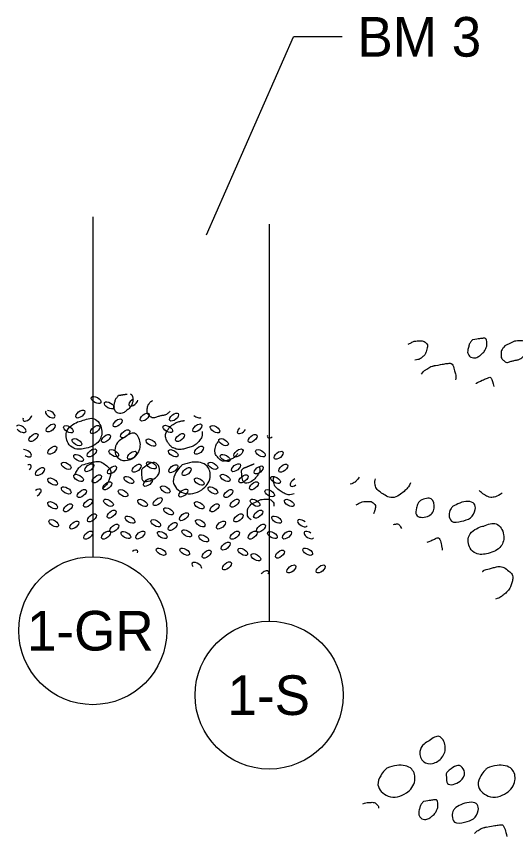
# Model space of a CAD drawing. Extents: x 1785 to 2465, y -264 to 295.
# Drawn here: x 2155.1 to 2190.3, y -12 to 45.9 of the extents above; entities that cross this region are included whole.
import ezdxf

# ---------------------------------------------------------------- set-up
doc = ezdxf.new("R2010")
doc.units = 0
for name, color, linetype in [('DR_P_Culvert', 7, 'Continuous'), ('DR_X_Erosion_Control', 7, 'Continuous'), ('PV_P_Shoulder', 7, 'Continuous'), ('TX_P_1', 7, 'Continuous'), ('TX_P_10', 7, 'Continuous')]:
    doc.layers.add(name, color=color, linetype=linetype)

msp = doc.modelspace()

# ---------------------------------------------------------------- linework, layer by layer
at = {"layer": 'DR_P_Culvert'}
for p, q in [((2160.483, 31.763), (2160.483, 7.757)), ((2172.931, 31.247), (2172.931, 3.206))]:
    msp.add_line(p, q, dxfattribs=at)
at = {"layer": 'DR_X_Erosion_Control'}
for centre, major_axis in [((2160.722, 18.823), (0.33, -0.195)), ((2161.645, 18.444), (0.33, -0.195)), ((2159.602, 17.833), (0.296, 0.243)), ((2162.234, 17.203), (0.296, 0.243)), ((2164.154, 17.618), (0.296, 0.243)), ((2166.226, 17.618), (0.296, 0.243)), ((2157.519, 16.85), (0.296, 0.243)), ((2158.76, 16.761), (0.33, -0.195)), ((2160.654, 16.735), (0.296, 0.243)), ((2165.78, 16.78), (0.33, -0.195)), ((2167.869, 16.85), (0.296, 0.243)), ((2169.11, 16.761), (0.33, -0.195)), ((2156.298, 16.172), (0.296, 0.243)), ((2161.413, 16.104), (0.296, 0.243)), ((2162.771, 16.433), (0.296, 0.243)), ((2166.647, 16.172), (0.296, 0.243)), ((2171.763, 16.104), (0.296, 0.243)), ((2159.365, 15.844), (0.33, -0.195)), ((2164.588, 15.816), (0.33, -0.195)), ((2169.715, 15.844), (0.33, -0.195)), ((2157.628, 15.276), (0.296, 0.243)), ((2160.419, 15.085), (0.296, 0.243)), ((2161.965, 15.066), (0.33, -0.195)), ((2163.252, 14.921), (0.296, 0.243)), ((2166.16, 15.064), (0.33, -0.195)), ((2167.978, 15.276), (0.296, 0.243)), ((2170.768, 15.085), (0.296, 0.243)), ((2172.315, 15.066), (0.33, -0.195)), ((2173.601, 14.921), (0.296, 0.243)), ((2159.479, 14.73), (0.33, -0.195)), ((2164.621, 14.21), (0.33, -0.195)), ((2169.828, 14.73), (0.33, -0.195)), ((2156.76, 13.771), (0.296, 0.243)), ((2158.612, 14.176), (0.33, -0.195)), ((2160.242, 14.044), (0.296, 0.243)), ((2161.846, 13.883), (0.296, 0.243)), ((2163.581, 14.005), (0.296, 0.243)), ((2166.167, 13.974), (0.296, 0.243)), ((2167.11, 13.771), (0.296, 0.243)), ((2168.961, 14.176), (0.33, -0.195)), ((2170.592, 14.044), (0.296, 0.243)), ((2172.196, 13.883), (0.296, 0.243)), ((2173.93, 14.005), (0.296, 0.243)), ((2157.646, 13.063), (0.33, -0.195)), ((2159.479, 13.322), (0.33, -0.195)), ((2160.772, 13.259), (0.296, 0.243)), ((2163.033, 13.178), (0.33, -0.195)), ((2164.378, 13.007), (0.296, 0.243)), ((2167.996, 13.063), (0.33, -0.195)), ((2169.828, 13.322), (0.33, -0.195)), ((2171.122, 13.259), (0.296, 0.243)), ((2173.383, 13.178), (0.33, -0.195)), ((2161.508, 12.767), (0.296, 0.243)), ((2165.604, 12.506), (0.33, -0.195)), ((2171.858, 12.767), (0.296, 0.243)), ((2158.612, 12.441), (0.33, -0.195)), ((2159.712, 12.223), (0.296, 0.243)), ((2162.622, 12.244), (0.33, -0.195)), ((2166.877, 12.256), (0.296, 0.243)), ((2168.961, 12.441), (0.33, -0.195)), ((2170.061, 12.223), (0.296, 0.243)), ((2172.971, 12.244), (0.33, -0.195)), ((2157.646, 11.392), (0.33, -0.195)), ((2160.152, 11.541), (0.296, 0.243)), ((2161.593, 11.568), (0.33, -0.195)), ((2163.998, 11.556), (0.33, -0.195)), ((2165.073, 11.649), (0.296, 0.243)), ((2167.996, 11.392), (0.33, -0.195)), ((2170.502, 11.541), (0.296, 0.243)), ((2171.943, 11.568), (0.33, -0.195)), ((2174.348, 11.556), (0.33, -0.195)), ((2158.729, 11.207), (0.296, 0.243)), ((2161.812, 10.761), (0.296, 0.243)), ((2165.833, 10.966), (0.33, -0.195)), ((2169.078, 11.207), (0.296, 0.243)), ((2172.161, 10.761), (0.296, 0.243)), ((2160.422, 10.499), (0.296, 0.243)), ((2163.113, 10.376), (0.33, -0.195)), ((2166.916, 10.585), (0.296, 0.243)), ((2170.771, 10.499), (0.296, 0.243)), ((2173.463, 10.376), (0.33, -0.195)), ((2157.724, 10.124), (0.33, -0.195)), ((2159.187, 9.995), (0.296, 0.243)), ((2162.005, 9.772), (0.296, 0.243)), ((2164.93, 10.124), (0.33, -0.195)), ((2166.119, 9.894), (0.296, 0.243)), ((2168.074, 10.124), (0.33, -0.195)), ((2169.537, 9.995), (0.296, 0.243)), ((2172.355, 9.772), (0.296, 0.243)), ((2160.162, 9.274), (0.296, 0.243)), ((2161.413, 9.285), (0.296, 0.243)), ((2162.82, 9.289), (0.33, -0.195)), ((2163.84, 9.289), (0.296, 0.243)), ((2165.392, 9.289), (0.33, -0.195)), ((2167.12, 9.407), (0.33, -0.195)), ((2168.318, 9.054), (0.33, -0.195)), ((2170.512, 9.274), (0.296, 0.243)), ((2171.763, 9.285), (0.296, 0.243)), ((2173.169, 9.289), (0.33, -0.195)), ((2174.189, 9.289), (0.296, 0.243)), ((2169.87, 8.512), (0.296, 0.243)), ((2165.309, 8.112), (0.33, -0.195)), ((2166.98, 8.112), (0.33, -0.195)), ((2168.52, 7.942), (0.296, 0.243)), ((2171.071, 8.101), (0.33, -0.195)), ((2173.692, 7.942), (0.296, 0.243)), ((2175.658, 8.112), (0.33, -0.195)), ((2171.995, 7.722), (0.33, -0.195)), ((2169.952, 7.111), (0.296, 0.243)), ((2174.503, 6.896), (0.296, 0.243)), ((2176.576, 6.896), (0.296, 0.243))]:
    msp.add_ellipse(centre, major_axis=major_axis, ratio=0.503326, dxfattribs=at)
for centre, major_axis, start_param, end_param in [((2163.343, 18.664), (0.296, 0.243), 1.141555, 5.825958), ((2157.482, 17.822), (0.33, -0.195), 2.991296, 6.283185), ((2157.482, 17.822), (0.33, -0.195), 0, 2.445726), ((2155.877, 17.618), (0.296, 0.243), 2.425489, 5.655565), ((2167.831, 17.822), (0.33, -0.195), 4.359513, 6.060101), ((2155.43, 16.78), (0.33, -0.195), 0, 3.21858), ((2171.004, 16.735), (0.296, 0.243), 1.695558, 5.271956), ((2155.43, 16.78), (0.33, -0.195), 4.059996, 6.283185), ((2173.121, 16.433), (0.296, 0.243), 2.541098, 4.426415), ((2155.81, 15.064), (0.33, -0.195), 0, 2.578544), ((2155.81, 15.064), (0.33, -0.195), 4.700032, 6.283185), ((2155.818, 13.974), (0.296, 0.243), 0, 0.904101), ((2155.818, 13.974), (0.296, 0.243), 4.961839, 6.283185), ((2174.727, 13.007), (0.296, 0.243), 1.12582, 4.595097), ((2156.527, 12.256), (0.296, 0.243), 0, 1.442135), ((2156.527, 12.256), (0.296, 0.243), 4.423805, 6.283185), ((2175.28, 10.124), (0.33, -0.195), 1.290497, 6.283185), ((2175.28, 10.124), (0.33, -0.195), 0, 0.072289), ((2175.742, 9.289), (0.33, -0.195), 1.43145, 6.214521), ((2163.343, 7.942), (0.296, 0.243), 0, 1.385311), ((2163.343, 7.942), (0.296, 0.243), 5.616836, 6.283185), ((2167.831, 7.1), (0.33, -0.195), 0.133342, 4.085911), ((2172.583, 6.481), (0.296, 0.243), 0, 1.910623), ((2172.583, 6.481), (0.296, 0.243), 5.471401, 6.283185)]:
    msp.add_ellipse(centre, major_axis=major_axis, ratio=0.503326, start_param=start_param, end_param=end_param, dxfattribs=at)
at = {"layer": 'PV_P_Shoulder'}
for points, degree in [([(2187.284, 23.07), (2187.539, 23.107), (2187.793, 23.147), (2188.048, 23.182), (2188.275, 23.212), (2188.328, 22.721), (2188.256, 22.525), (2188.177, 22.308), (2187.98, 22.092), (2187.776, 21.937), (2187.566, 21.776), (2187.124, 21.803), (2187.003, 22.05), (2186.926, 22.205), (2186.965, 22.386), (2187.008, 22.542), (2187.038, 22.651), (2187.053, 22.777), (2187.124, 22.868), (2187.178, 22.936), (2187.231, 23.003), (2187.284, 23.07)], 3), ([(2182.745, 22.765), (2182.826, 22.806), (2182.907, 22.846), (2182.988, 22.887), (2183.171, 22.978), (2183.39, 22.996), (2183.589, 23.002), (2183.737, 23.006), (2183.878, 22.971), (2184.011, 22.84), (2184.132, 22.72), (2184.115, 22.56), (2184.079, 22.433), (2184.02, 22.223), (2183.942, 22.01), (2183.738, 21.84), (2183.572, 21.702), (2183.399, 21.662), (2183.223, 21.624)], 3), ([(2189.559, 22.637), (2189.726, 22.72), (2189.892, 22.803), (2190.059, 22.887), (2190.242, 22.978), (2190.462, 22.996), (2190.661, 23.002), (2190.808, 23.006), (2190.95, 22.971), (2191.083, 22.84), (2191.204, 22.72), (2191.187, 22.56), (2191.151, 22.433), (2191.092, 22.223), (2191.014, 22.01), (2190.809, 21.84), (2190.609, 21.674), (2190.398, 21.65), (2190.183, 21.6), (2189.957, 21.547), (2189.7, 21.414), (2189.479, 21.612), (2189.334, 21.742), (2189.304, 21.894), (2189.308, 22.043), (2189.311, 22.176), (2189.328, 22.332), (2189.411, 22.443), (2189.46, 22.509), (2189.51, 22.572), (2189.559, 22.637)], 3), ([(2184.661, 21.258), (2184.964, 21.31), (2185.267, 21.368), (2185.569, 21.41), (2185.872, 21.452), (2186.012, 20.934), (2186.088, 20.65), (2186.122, 20.522), (2186.128, 20.379), (2186.099, 20.239)], 3), ([(2183.696, 20.653), (2183.79, 20.792), (2183.912, 20.915), (2184.061, 21.01), (2184.209, 21.104), (2184.349, 21.192), (2184.513, 21.227), (2184.568, 21.238), (2184.623, 21.25), (2184.678, 21.262)], 3), ([(2187.693, 20.093), (2187.927, 20.194), (2188.162, 20.294), (2188.396, 20.395), (2188.622, 20.492), (2188.741, 20.037), (2188.799, 19.773)], 3), ([(2187.535, 19.991), (2187.587, 20.025), (2187.64, 20.059), (2187.693, 20.093)], 2), ([(2163.143, 19.255), (2163.308, 19.183), (2163.341, 18.782), (2163.278, 18.608), (2163.199, 18.392), (2163.002, 18.176), (2162.798, 18.02), (2162.588, 17.86), (2162.146, 17.886), (2162.025, 18.133), (2161.948, 18.289), (2161.986, 18.469), (2162.03, 18.625), (2162.06, 18.735), (2162.074, 18.861), (2162.146, 18.952), (2162.2, 19.019), (2162.253, 19.086), (2162.306, 19.153)], 3), ([(2162.306, 19.153), (2162.507, 19.182), (2162.707, 19.214), (2162.907, 19.242)], 2), ([(2165.933, 18.023), (2165.903, 17.989), (2165.869, 17.955), (2165.831, 17.923), (2165.631, 17.757), (2165.419, 17.733), (2165.205, 17.683), (2164.979, 17.631), (2164.721, 17.497), (2164.501, 17.695), (2164.356, 17.826), (2164.326, 17.978), (2164.33, 18.127), (2164.333, 18.259), (2164.349, 18.416), (2164.433, 18.527), (2164.482, 18.592), (2164.532, 18.656), (2164.581, 18.72)], 3), ([(2164.581, 18.72), (2164.624, 18.742), (2164.667, 18.763), (2164.71, 18.785)], 2), ([(2166.755, 17.342), (2166.826, 17.354), (2166.897, 17.366), (2166.968, 17.379)], 2), ([(2168.205, 16.609), (2168.232, 16.379), (2168.171, 16.123), (2167.988, 15.92), (2167.721, 15.625), (2167.425, 15.512), (2167.096, 15.415), (2166.814, 15.332), (2166.497, 15.302), (2166.216, 15.42), (2166.045, 15.492), (2165.921, 15.616), (2165.818, 15.777), (2165.645, 16.044), (2165.594, 16.414), (2165.745, 16.667), (2165.845, 16.834), (2165.98, 16.982), (2166.155, 17.093), (2166.302, 17.187), (2166.443, 17.275), (2166.606, 17.31), (2166.661, 17.322), (2166.716, 17.333), (2166.771, 17.345)], 3), ([(2170.721, 15.042), (2170.708, 15.025), (2170.695, 15.008), (2170.681, 14.992), (2170.482, 14.753), (2170.254, 14.639), (2170.015, 14.567), (2169.823, 14.509), (2169.581, 14.499), (2169.393, 14.685), (2169.165, 14.91), (2169.081, 15.174), (2169.126, 15.403), (2169.158, 15.563), (2169.227, 15.767), (2169.358, 15.891)], 3), ([(2156.78, 15.621), (2156.78, 15.616), (2156.78, 15.611), (2156.78, 15.607)], 2), ([(2159.725, 14.238), (2159.962, 14.302), (2160.199, 14.364), (2160.436, 14.425), (2160.783, 14.515), (2161.131, 14.451), (2161.478, 14.162), (2161.747, 13.937), (2161.764, 13.605), (2161.693, 13.357), (2161.609, 13.065), (2161.432, 12.788), (2161.164, 12.542)], 3), ([(2159.225, 13.594), (2159.245, 13.63), (2159.265, 13.665), (2159.286, 13.698), (2159.372, 13.835), (2159.449, 13.973), (2159.563, 14.083), (2159.617, 14.135), (2159.67, 14.187), (2159.725, 14.238)], 3), ([(2172.243, 14.095), (2172.258, 14.035), (2172.267, 13.977), (2172.271, 13.935), (2172.29, 13.736), (2172.137, 13.528), (2171.973, 13.33), (2171.75, 13.062), (2171.189, 12.867), (2171.073, 13.162), (2171.011, 13.318), (2171.001, 13.48), (2170.995, 13.642), (2170.991, 13.722), (2170.961, 13.811), (2171.003, 13.883), (2171.024, 13.92), (2171.048, 13.952), (2171.07, 13.987)], 3), ([(2171.07, 13.987), (2171.341, 14.096), (2171.612, 14.212), (2171.883, 14.319)], 2), ([(2174.69, 12.189), (2174.433, 12.119), (2174.168, 12.135), (2173.948, 12.265), (2173.633, 12.452), (2173.3, 12.731), (2173.24, 13.062), (2173.217, 13.182), (2173.245, 13.313), (2173.295, 13.44)], 3), ([(2179.299, 13.383), (2179.25, 13.311), (2179.193, 13.239), (2179.135, 13.169), (2179.024, 13.035), (2178.829, 12.919), (2178.647, 12.874)], 3), ([(2182.915, 12.973), (2182.807, 12.741), (2182.637, 12.522), (2182.406, 12.325), (2182.026, 12.001), (2181.499, 11.873), (2181.11, 12.104), (2180.795, 12.29), (2180.462, 12.57), (2180.401, 12.9), (2180.381, 13.012), (2180.403, 13.134), (2180.447, 13.253)], 3), ([(2189.37, 12.241), (2189.002, 11.98), (2188.534, 11.894), (2188.181, 12.104), (2188.033, 12.191), (2187.881, 12.3), (2187.756, 12.424)], 3), ([(2171.653, 11.459), (2171.819, 11.543), (2171.986, 11.626), (2172.153, 11.709), (2172.336, 11.8), (2172.555, 11.818), (2172.755, 11.824), (2172.902, 11.828), (2173.044, 11.794), (2173.176, 11.662), (2173.277, 11.562), (2173.282, 11.434), (2173.26, 11.321)], 3), ([(2179.081, 11.431), (2179.158, 11.47), (2179.237, 11.509), (2179.315, 11.548), (2179.498, 11.639), (2179.717, 11.657), (2179.916, 11.663), (2180.063, 11.667), (2180.205, 11.632), (2180.338, 11.501), (2180.459, 11.381), (2180.442, 11.221), (2180.406, 11.094), (2180.378, 10.992), (2180.344, 10.888), (2180.294, 10.789)], 3), ([(2171.675, 10.366), (2171.641, 10.382), (2171.606, 10.404), (2171.573, 10.434), (2171.427, 10.565), (2171.397, 10.717), (2171.401, 10.866), (2171.405, 10.998), (2171.421, 11.155), (2171.505, 11.266), (2171.554, 11.331), (2171.603, 11.395), (2171.653, 11.459)], 3), ([(2181.706, 10.043), (2181.77, 10.053), (2181.833, 10.062), (2181.896, 10.071), (2182.069, 10.095), (2182.189, 9.936), (2182.274, 9.742)], 3), ([(2184.088, 8.783), (2184.299, 8.874), (2184.511, 8.965), (2184.723, 9.056), (2184.966, 9.16), (2185.085, 8.627), (2185.138, 8.379), (2185.149, 8.327), (2185.156, 8.273), (2185.157, 8.218)], 3), ([(2188.101, 6.816), (2188.338, 6.879), (2188.576, 6.941), (2188.813, 7.003), (2189.159, 7.092), (2189.508, 7.029), (2189.855, 6.739), (2190.123, 6.515), (2190.141, 6.182), (2190.07, 5.934), (2189.98, 5.621), (2189.782, 5.324), (2189.478, 5.064), (2189.307, 4.919), (2189.107, 4.813), (2188.903, 4.761)], 3), ([(2187.997, 6.716), (2188.032, 6.75), (2188.066, 6.783), (2188.101, 6.816)], 2), ([(2179.542, -9.69), (2179.723, -9.604), (2179.937, -9.587), (2180.132, -9.581), (2180.279, -9.577), (2180.421, -9.611), (2180.554, -9.743), (2180.626, -9.814), (2180.649, -9.9), (2180.649, -9.985)], 3), ([(2183.827, -9.513), (2184.082, -9.476), (2184.336, -9.436), (2184.591, -9.401), (2184.818, -9.37), (2184.871, -9.861), (2184.799, -10.058), (2184.72, -10.274), (2184.523, -10.49), (2184.319, -10.646), (2184.109, -10.807), (2183.667, -10.78), (2183.546, -10.533), (2183.469, -10.377), (2183.507, -10.197), (2183.551, -10.041), (2183.581, -9.931), (2183.596, -9.805), (2183.667, -9.714), (2183.721, -9.647), (2183.774, -9.58), (2183.827, -9.513)], 3), ([(2187.423, -11.786), (2187.496, -11.706), (2187.58, -11.634), (2187.676, -11.573), (2187.823, -11.479), (2187.964, -11.391), (2188.127, -11.356), (2188.182, -11.344), (2188.237, -11.333), (2188.292, -11.321)], 3), ([(2188.276, -11.324), (2188.578, -11.273), (2188.881, -11.215), (2189.184, -11.173), (2189.486, -11.131), (2189.627, -11.649), (2189.702, -11.933), (2189.708, -11.955), (2189.713, -11.977), (2189.717, -12)], 3)]:
    msp.add_open_spline(points, degree=degree, dxfattribs=at)
for points in [[(2159.683, 17.342), (2160.591, 17.493), (2161.11, 16.733), (2160.916, 15.92), (2160.025, 15.415), (2159.145, 15.42), (2158.746, 15.777), (2158.673, 16.667), (2159.083, 17.093), (2159.535, 17.31), (2159.7, 17.345)], [(2162.715, 16.177), (2163.418, 16.478), (2163.833, 15.802), (2163.61, 14.992), (2162.943, 14.567), (2162.321, 14.685), (2162.055, 15.403), (2162.346, 15.938), (2162.715, 16.177)], [(2163.998, 13.987), (2164.948, 14.372), (2165.2, 13.935), (2164.901, 13.33), (2164.001, 13.162), (2163.923, 13.642), (2163.931, 13.883), (2163.998, 13.987)], [(2166.796, 14.238), (2167.508, 14.425), (2168.55, 14.162), (2168.765, 13.357), (2168.173, 12.487), (2166.876, 12.265), (2166.168, 13.062), (2166.358, 13.698), (2166.635, 14.083), (2166.796, 14.238)], [(2183.611, 11.731), (2184.375, 11.843), (2184.583, 11.186), (2184.103, 10.598), (2183.33, 10.711), (2183.335, 11.203), (2183.451, 11.529), (2183.611, 11.731)], [(2185.886, 11.298), (2186.386, 11.548), (2186.988, 11.663), (2187.41, 11.501), (2187.478, 11.094), (2187.136, 10.501), (2186.51, 10.261), (2185.806, 10.273), (2185.635, 10.704), (2185.738, 11.104), (2185.886, 11.298)], [(2188.06, 9.919), (2188.968, 10.071), (2189.486, 9.311), (2189.293, 8.498), (2188.401, 7.993), (2187.521, 7.998), (2187.123, 8.354), (2187.05, 9.244), (2187.46, 9.671), (2187.911, 9.888), (2188.076, 9.923)], [(2184.236, -5.228), (2184.939, -4.927), (2185.354, -5.603), (2185.131, -6.413), (2184.464, -6.838), (2183.842, -6.72), (2183.576, -6.002), (2183.867, -5.467), (2184.236, -5.228)], [(2181.246, -7.167), (2181.957, -6.98), (2182.999, -7.243), (2183.214, -8.048), (2182.622, -8.918), (2181.326, -9.14), (2180.617, -8.343), (2180.807, -7.707), (2181.084, -7.322), (2181.246, -7.167)], [(2185.519, -7.418), (2186.469, -7.033), (2186.721, -7.47), (2186.422, -8.075), (2185.522, -8.243), (2185.444, -7.763), (2185.452, -7.522), (2185.519, -7.418)], [(2188.317, -7.167), (2189.029, -6.98), (2190.071, -7.243), (2190.286, -8.048), (2189.694, -8.918), (2188.397, -9.14), (2187.689, -8.343), (2187.879, -7.707), (2188.156, -7.322), (2188.317, -7.167)], [(2186.102, -9.946), (2186.602, -9.696), (2187.204, -9.581), (2187.626, -9.743), (2187.694, -10.149), (2187.352, -10.743), (2186.726, -10.983), (2186.022, -10.971), (2185.851, -10.539), (2185.954, -10.139), (2186.102, -9.946)]]:
    msp.add_spline(points, degree=3, dxfattribs=at)
at = {"layer": 'TX_P_1'}
for centre in [(2160.483, 2.535), (2172.931, -2.015)]:
    msp.add_circle(centre, 5.222, dxfattribs=at)
at = {"layer": 'TX_P_10'}
for p in [(2168.512, 30.476), (2178.081, 44.462)]:
    msp.add_line(p, (2174.653, 44.462), dxfattribs=at)

# ---------------------------------------------------------------- texts
at = {"layer": 'TX_P_1'}
for s, p in [('1-GR', (2155.837, 1.135)), ('1-S', (2169.99, -3.415))]:
    msp.add_text(s, height=2.8, dxfattribs=at).set_placement(p)
at = {"layer": 'TX_P_10'}
msp.add_text('BM 3', height=2.8, dxfattribs=at).set_placement((2179.164, 43.062))

doc.saveas('drawing.dxf')
